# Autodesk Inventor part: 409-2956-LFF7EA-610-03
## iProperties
Created: 2011-01
Part Number: 409-2956-LFF7EA-610-03
Cost Center: 0 lbmass
Material: A36 STEEL PLATE
Document SubType Name: Sheet Metal
Designer: S. Boerckel
Authority: 0 in^3
Mass: 2366.74 g
Surface Area: 564.515 cm^2
Volume: 301.112 cm^3
Density: 7.86 g/cm^3
Flat Pattern Width: 8.89 cm
Flat Pattern Length: 26.67 cm
Flat Pattern Area: 237.096 cm^2
Sheet Metal Rule: 1/2"Thk
Description: BASE PLATE
SaveDate: 2008-01-15
SaveTime: 10:24
FileName: Sheet Metal
Wide: =<Flat Pattern Width>cm
Length: =<Flat Pattern Length>cm
Thickness: 0.5000 in
SMR: =<Sheet Metal Rule> - <Material>
Author: S. Boerckel
Revision Number: 0
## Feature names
1. Plate1
